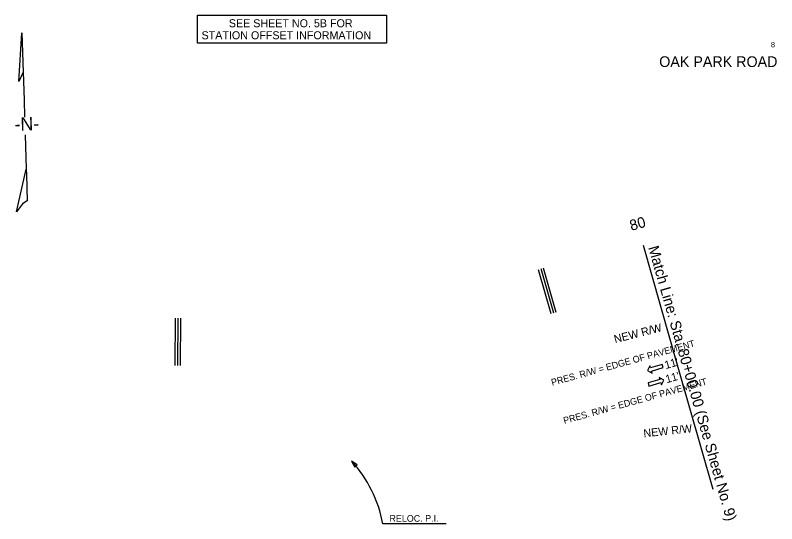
# Model space of a CAD drawing. Extents: x 1964377 to 1966966, y 1116414 to 1123213.
# Drawn here: x 1966366 to 1966937, y 1119377 to 1119757 of the extents above; entities that cross this region are included whole.
import ezdxf

# ---------------------------------------------------------------- set-up
doc = ezdxf.new("R2010")
doc.units = 0
for name, color, linetype in [('RD_EX_Misc', 7, 'Continuous'), ('RD_EX_RW_TX', 7, 'Continuous'), ('RD_HC_Data', 7, 'Continuous'), ('RD_HC_Data_Rel', 7, 'Continuous'), ('RD_HC_TX_Rel_Sta50', 7, 'Continuous'), ('RD_PD_Final_LnLine', 7, 'Continuous'), ('RD_PD_Final_TX', 7, 'Continuous'), ('RD_PD_RW_TX', 7, 'Continuous'), ('RD_SHT_MatchLine', 7, 'Continuous'), ('RD_SHT_TX', 7, 'Continuous'), ('RD_TX_StaOff', 7, 'Continuous')]:
    doc.layers.add(name, color=color, linetype=linetype)

msp = doc.modelspace()

# ---------------------------------------------------------------- linework, layer by layer
at = {"layer": 'RD_EX_Misc'}
for p, q in [((1966368.94, 1119707.76), (1966371.1, 1119744.24)), ((1966371.1, 1119744.24), (1966372.05, 1119714.62)), ((1966372.05, 1119714.62), (1966368.94, 1119707.76)), ((1966372.05, 1119714.62), (1966372.71, 1119694.09)), ((1966372.71, 1119694.09), (1966373.13, 1119680.99)), ((1966373.55, 1119667.92), (1966374.39, 1119642.04)), ((1966367.16, 1119610.05), (1966374.39, 1119642.04)), ((1966374.39, 1119642.04), (1966374.51, 1119638.12)), ((1966374.51, 1119638.12), (1966375.15, 1119618.28))]:
    msp.add_line(p, q, dxfattribs=at)
msp.add_lwpolyline([(1966375.15, 1119618.28), (1966371.67, 1119616.23), (1966367.16, 1119610.05)], dxfattribs=at)
at = {"layer": 'RD_HC_Data'}
for p, q in [((1966771.45, 1119534.79), (1966761.96, 1119567.9)), ((1966767.61, 1119533.69), (1966758.12, 1119566.8)), ((1966769.53, 1119534.24), (1966760.04, 1119567.35)), ((1966485.96, 1119495), (1966486.23, 1119530.42)), ((1966487.96, 1119494.98), (1966488.23, 1119530.4)), ((1966489.96, 1119494.97), (1966490.23, 1119530.39))]:
    msp.add_line(p, q, dxfattribs=at)
at = {"layer": 'RD_HC_Data_Rel'}
msp.add_line((1966688.93, 1119376.54), (1966641.49, 1119376.54), dxfattribs=at)
msp.add_lwpolyline([(1966622.39, 1119420.73), (1966618.17, 1119423.42), (1966620.48, 1119418.98)], close=True, dxfattribs=at)
msp.add_arc((1966548.42, 1119359.49), 94.62, 10.3818, 42.5076, dxfattribs=at)
at = {"layer": 'RD_PD_Final_LnLine'}
for points in [[(1966851.56, 1119493.45), (1966850.9, 1119495.76), (1966842.08, 1119493.23), (1966841.64, 1119494.8), (1966839.7, 1119491.3), (1966843.19, 1119489.36), (1966842.75, 1119490.93)], [(1966840.25, 1119482), (1966840.91, 1119479.69), (1966849.73, 1119482.22), (1966850.18, 1119480.65), (1966852.12, 1119484.15), (1966848.62, 1119486.09), (1966849.07, 1119484.52)]]:
    msp.add_lwpolyline(points, close=True, dxfattribs=at)
at = {"layer": 'RD_SHT_MatchLine'}
msp.add_lwpolyline([(1966889.06, 1119402.22), (1966862.89, 1119493.55), (1966836.72, 1119584.87)], dxfattribs=at)
at = {"layer": 'RD_TX_StaOff'}
msp.add_lwpolyline([(1966502.65, 1119757.37), (1966644.19, 1119757.37), (1966644.19, 1119736.37), (1966502.65, 1119736.37)], close=True, dxfattribs=at)

# ---------------------------------------------------------------- texts
at = {"layer": 'RD_EX_Misc'}
msp.add_text('-N-', height=10, rotation=1.8413, dxfattribs=at).set_placement((1966365.67, 1119670.81))
at = {"layer": 'RD_EX_RW_TX'}
for p in [(1966768.44, 1119479.84), (1966777.52, 1119451.27)]:
    msp.add_text('PRES. R/W = EDGE OF PAVEMENT', height=5, rotation=15.437, dxfattribs=at).set_placement(p)
at = {"layer": 'RD_HC_Data_Rel'}
msp.add_text('RELOC. P.I.', height=5, dxfattribs=at).set_placement((1966646.49, 1119378.04))
at = {"layer": 'RD_HC_TX_Rel_Sta50'}
msp.add_text('80', height=8, rotation=15.9906, dxfattribs=at).set_placement((1966827.72, 1119595.82))
at = {"layer": 'RD_PD_Final_TX'}
for p in [(1966853.54, 1119492.33), (1966854.22, 1119481.77)]:
    msp.add_text("11'", height=6, rotation=15.9906, dxfattribs=at).set_placement(p)
at = {"layer": 'RD_PD_RW_TX'}
for rotation, p in [(14.3368, (1966815.56, 1119511.75)), (6.0211, (1966837.09, 1119441.24))]:
    msp.add_text('NEW R/W', height=6, rotation=rotation, dxfattribs=at).set_placement(p)
at = {"layer": 'RD_SHT_MatchLine'}
msp.add_text('Match Line: Sta. 80+00.00 (See Sheet No. 9)', height=8, rotation=285.9906, dxfattribs=at).set_placement((1966840.25, 1119583.44))
at = {"layer": 'RD_SHT_TX'}
for s, height, p in [('8', 4, (1966932.27, 1119733.35)), ('OAK PARK ROAD', 8, (1966848.59, 1119718.61))]:
    msp.add_text(s, height=height, dxfattribs=at).set_placement(p)
at = {"layer": 'RD_TX_StaOff'}
for s, p in [('SEE SHEET NO. 5B FOR', (1966526.15, 1119748.37)), ('STATION OFFSET INFORMATION', (1966505.73, 1119739.37))]:
    msp.add_text(s, height=6, dxfattribs=at).set_placement(p)

doc.saveas('drawing.dxf')
